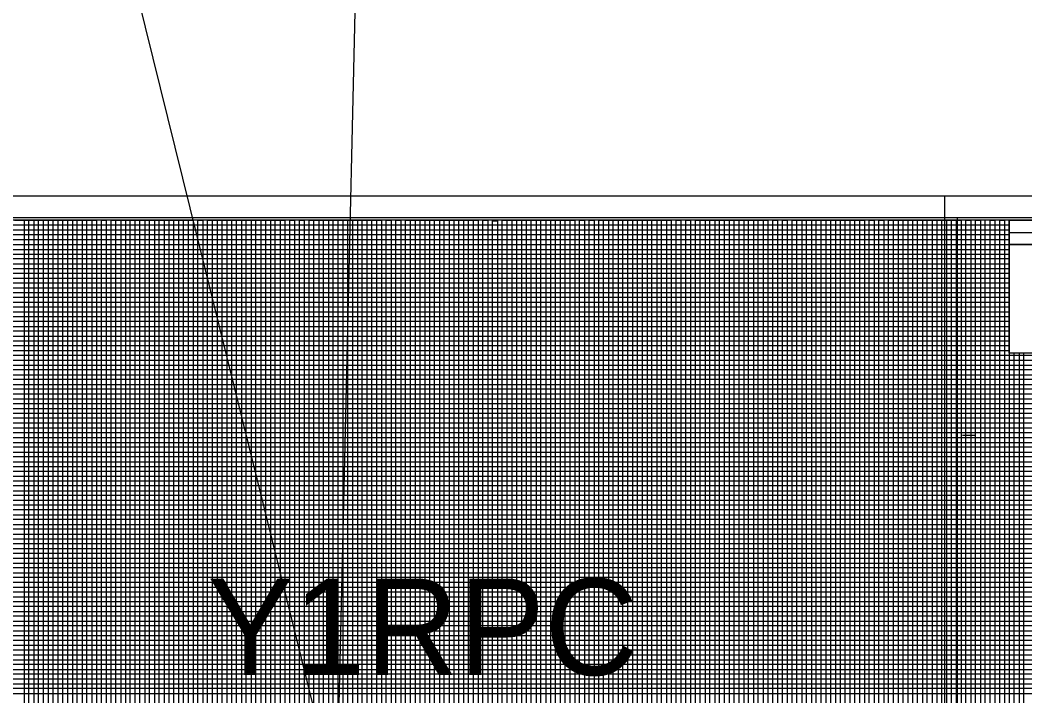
# Model space of a CAD drawing. Extents: x 2345490 to 2436403, y 465165 to 573888.
# Drawn here: x 2411121 to 2412161, y 509253 to 509953 of the extents above; entities that cross this region are included whole.
import ezdxf

# ---------------------------------------------------------------- set-up
doc = ezdxf.new("R2010")
doc.units = 0
for name, color, linetype in [('Old_Level_18', 7, 'Continuous'), ('Old_Level_2', 7, 'Continuous'), ('Old_Level_3', 7, 'Continuous'), ('Old_Level_40', 7, 'Continuous'), ('Old_Level_41', 7, 'Continuous'), ('Old_Level_42', 7, 'Continuous'), ('Old_Level_43', 7, 'Continuous'), ('Old_Level_50', 7, 'Continuous'), ('Old_Level_51', 7, 'Continuous')]:
    doc.layers.add(name, color=color, linetype=linetype)

msp = doc.modelspace()

# ---------------------------------------------------------------- linework, layer by layer
at = {"layer": 'Old_Level_18'}
msp.add_lwpolyline([(2412345.325, 509745.412), (2410845.325, 509745.412), (2410845.325, 508695.412), (2412345.325, 508695.412)], close=True, dxfattribs=at)
at = {"layer": 'Old_Level_2'}
for p, q in [((2408459.41, 521238.414), (2413898.04625, 499235.39575)), ((2411722.59175, 521117.51825), (2411239.1575, 499960.77))]:
    msp.add_line(p, q, dxfattribs=at)
at = {"layer": 'Old_Level_40'}
msp.add_line((2412145.275, 509732.862), (2412345.325, 509732.862), dxfattribs=at)
for points in [[(2412145.275, 509745.412), (2412345.325, 509745.412), (2412345.325, 509720.362), (2412145.275, 509720.362)], [(2412145.275, 509720.362), (2412245.325, 509720.362), (2412245.325, 509607.862), (2412145.275, 509607.862)]]:
    msp.add_lwpolyline(points, close=True, dxfattribs=at)
at = {"layer": 'Old_Level_41'}
msp.add_line((2412096.825, 509522.912), (2412109.325, 509522.912), dxfattribs=at)
for points in [[(2411120.325, 509745.412), (2411170.325, 509745.412), (2411170.325, 508720.412)], [(2411145.325, 508720.412), (2411145.325, 509745.412), (2411195.325, 509745.412), (2411195.325, 508720.412)], [(2411220.325, 508720.412), (2411220.325, 509745.412), (2411270.325, 509745.412), (2411270.325, 508720.412)], [(2411245.325, 508720.412), (2411245.325, 509745.412), (2411295.325, 509745.412), (2411295.325, 508720.412)], [(2411320.325, 508720.412), (2411320.325, 509745.412), (2411370.325, 509745.412), (2411370.325, 508720.412)], [(2411345.325, 508720.412), (2411345.325, 509745.412), (2411395.325, 509745.412), (2411395.325, 508720.412)], [(2411420.325, 508720.412), (2411420.325, 509745.412), (2411470.325, 509745.412), (2411470.325, 508720.412)], [(2411445.325, 508720.412), (2411445.325, 509745.412), (2411495.325, 509745.412), (2411495.325, 508720.412)], [(2411520.325, 508720.412), (2411520.325, 509745.412), (2411570.325, 509745.412), (2411570.325, 508720.412)], [(2411545.325, 508720.412), (2411545.325, 509745.412), (2411595.325, 509745.412), (2411595.325, 508720.412)], [(2411620.325, 508720.412), (2411620.325, 509745.412), (2411670.325, 509745.412), (2411670.325, 508720.412)], [(2411645.325, 508720.412), (2411645.325, 509745.412), (2411695.325, 509745.412), (2411695.325, 508720.412)], [(2411720.325, 508720.412), (2411720.325, 509745.412), (2411770.325, 509745.412), (2411770.325, 508720.412)], [(2411745.325, 508720.412), (2411745.325, 509745.412), (2411795.325, 509745.412), (2411795.325, 508720.412)], [(2411820.325, 508720.412), (2411820.325, 509745.412), (2411870.325, 509745.412), (2411870.325, 508720.412)], [(2411845.325, 508720.412), (2411845.325, 509745.412), (2411895.325, 509745.412), (2411895.325, 508720.412)], [(2411920.325, 508720.412), (2411920.325, 509745.412), (2411970.325, 509745.412), (2411970.325, 508720.412)], [(2411945.325, 508720.412), (2411945.325, 509745.412), (2411995.325, 509745.412), (2411995.325, 508720.412)], [(2412020.325, 508720.412), (2412020.325, 509745.412), (2412070.325, 509745.412), (2412070.325, 508720.412)], [(2412045.325, 508720.412), (2412045.325, 509745.412), (2412095.325, 509745.412), (2412095.325, 508720.412)], [(2412120.325, 508720.412), (2412120.325, 509745.412)], [(2412145.325, 508720.412), (2412145.325, 509745.412), (2412171.625, 509745.412)], [(2410845.325, 509695.412), (2412145.275, 509695.412)], [(2412145.275, 509645.412), (2410845.325, 509645.412), (2410845.325, 509595.362), (2412345.325, 509595.362)], [(2412345.325, 509570.412), (2410845.325, 509570.412), (2410845.325, 509620.412), (2412145.275, 509620.412)], [(2412345.325, 509545.412), (2410845.325, 509545.412), (2410845.325, 509495.412), (2412345.325, 509495.412)], [(2412345.325, 509470.412), (2410845.325, 509470.412), (2410845.325, 509520.412), (2412345.325, 509520.412)], [(2412345.325, 509445.412), (2410845.325, 509445.412), (2410845.325, 509395.412), (2412345.325, 509395.412)], [(2412345.325, 509345.412), (2410845.325, 509345.412), (2410845.325, 509295.412), (2412345.325, 509295.412)]]:
    msp.add_lwpolyline(points, dxfattribs=at)
at = {"layer": 'Old_Level_42'}
for points in [[(2412145.275, 509670.412), (2410845.425, 509670.412), (2410845.425, 509720.362), (2412145.275, 509720.362)], [(2412345.325, 509370.412), (2410845.325, 509370.412), (2410845.325, 509420.412), (2412345.325, 509420.412)], [(2412345.325, 509270.412), (2410845.325, 509270.412), (2410845.325, 509320.412), (2412345.325, 509320.412)]]:
    msp.add_lwpolyline(points, dxfattribs=at)
at = {"layer": 'Old_Level_43'}
for p, q in [((2412295.325, 509565.412), (2410895.325, 509565.412)), ((2410895.325, 509560.412), (2412295.325, 509560.412)), ((2412295.325, 509540.412), (2410895.325, 509540.412))]:
    msp.add_line(p, q, dxfattribs=at)
for points in [[(2411115.325, 509745.412), (2411125.325, 509745.412), (2411125.325, 508720.412)], [(2411130.325, 508720.412), (2411130.325, 509745.412), (2411135.325, 509745.412), (2411135.325, 508720.412)], [(2411140.325, 508720.412), (2411140.325, 509745.412), (2411150.325, 509745.412), (2411150.325, 508720.412)], [(2411155.325, 508720.412), (2411155.325, 509745.412), (2411160.325, 509745.412), (2411160.325, 508720.412)], [(2411165.325, 508720.412), (2411165.325, 509745.412), (2411175.325, 509745.412), (2411175.325, 508720.412)], [(2411180.325, 508720.412), (2411180.325, 509745.412), (2411185.325, 509745.412), (2411185.325, 508720.412)], [(2411190.325, 508720.412), (2411190.325, 509745.412), (2411200.325, 509745.412), (2411200.325, 508720.412)], [(2411205.325, 508720.412), (2411205.325, 509745.412), (2411210.325, 509745.412), (2411210.325, 508720.412)], [(2411215.325, 508720.412), (2411215.325, 509745.412), (2411225.325, 509745.412), (2411225.325, 508720.412)], [(2411230.325, 509745.412), (2411230.325, 508720.412), (2411235.325, 508720.412), (2411235.325, 509745.412)], [(2411240.325, 508720.412), (2411240.325, 509745.412), (2411250.325, 509745.412), (2411250.325, 508720.412)], [(2411255.325, 508720.412), (2411255.325, 509745.412), (2411260.325, 509745.412), (2411260.325, 508720.412)], [(2411265.325, 508720.412), (2411265.325, 509745.412), (2411275.325, 509745.412), (2411275.325, 508720.412)], [(2411280.325, 508720.412), (2411280.325, 509745.412), (2411285.325, 509745.412), (2411285.325, 508720.412)], [(2411290.325, 508720.412), (2411290.325, 509745.412), (2411300.325, 509745.412), (2411300.325, 508720.412)], [(2411305.325, 508720.412), (2411305.325, 509745.412), (2411310.325, 509745.412), (2411310.325, 508720.412)], [(2411315.325, 508720.412), (2411315.325, 509745.412), (2411325.325, 509745.412), (2411325.325, 508720.412)], [(2411330.325, 508720.412), (2411330.325, 509745.412), (2411335.325, 509745.412), (2411335.325, 508720.412)], [(2411340.325, 508720.412), (2411340.325, 509745.412), (2411350.325, 509745.412), (2411350.325, 508720.412)], [(2411355.325, 508720.412), (2411355.325, 509745.412), (2411360.325, 509745.412), (2411360.325, 508720.412)], [(2411365.325, 508720.412), (2411365.325, 509745.412), (2411375.325, 509745.412), (2411375.325, 508720.412)], [(2411380.325, 509745.412), (2411380.325, 508720.412), (2411385.325, 508720.412), (2411385.325, 509745.412), (2411390.325, 509745.412), (2411390.325, 508720.412), (2411400.325, 508720.412), (2411400.325, 509745.412), (2411405.325, 509745.412), (2411405.325, 508720.412), (2411410.325, 508720.412), (2411410.325, 509745.412), (2411415.325, 509745.412), (2411415.325, 508720.412)], [(2411425.325, 508720.412), (2411425.325, 509745.412), (2411430.325, 509745.412), (2411430.325, 508720.412)], [(2411435.325, 508720.412), (2411435.325, 509745.412), (2411440.325, 509745.412), (2411440.325, 508720.412)], [(2411450.325, 508720.412), (2411450.325, 509745.412), (2411455.325, 509745.412), (2411455.325, 508720.412)], [(2411460.325, 508720.412), (2411460.325, 509745.412), (2411465.325, 509745.412), (2411465.325, 508720.412)], [(2411475.325, 508720.412), (2411475.325, 509745.412), (2411480.325, 509745.412), (2411480.325, 508720.412)], [(2411485.325, 508720.412), (2411485.325, 509745.412), (2411490.325, 509745.412), (2411490.325, 508720.412)], [(2411500.325, 508720.412), (2411500.325, 509745.412), (2411505.325, 509745.412), (2411505.325, 508720.412)], [(2411510.325, 508720.412), (2411510.325, 509745.412), (2411515.325, 509745.412), (2411515.325, 508720.412)], [(2411525.325, 508720.412), (2411525.325, 509745.412), (2411530.325, 509745.412), (2411530.325, 508720.412)], [(2411535.325, 508720.412), (2411535.325, 509745.412), (2411540.325, 509745.412), (2411540.325, 508720.412)], [(2411550.325, 508720.412), (2411550.325, 509745.412), (2411555.325, 509745.412), (2411555.325, 508720.412)], [(2411560.325, 508720.412), (2411560.325, 509745.412), (2411565.325, 509745.412), (2411565.325, 508720.412)], [(2411575.325, 508720.412), (2411575.325, 509745.412), (2411580.325, 509745.412), (2411580.325, 508720.412)], [(2411585.325, 508720.412), (2411585.325, 509745.412), (2411590.325, 509745.412), (2411590.325, 508720.412)], [(2411600.325, 508720.412), (2411600.325, 509745.412), (2411605.325, 509745.412), (2411605.325, 508720.412)], [(2411625.325, 508720.412), (2411625.325, 509745.412), (2411630.325, 509745.412), (2411630.325, 508720.412)], [(2411635.325, 508720.412), (2411635.325, 509745.412), (2411640.325, 509745.412), (2411640.325, 508720.412)], [(2411650.325, 508720.412), (2411650.325, 509745.412), (2411655.325, 509745.412), (2411655.325, 508720.412)], [(2411660.325, 508720.412), (2411660.325, 509745.412), (2411665.325, 509745.412), (2411665.325, 508720.412)], [(2411675.325, 508720.412), (2411675.325, 509745.412), (2411680.325, 509745.412), (2411680.325, 508720.412)], [(2411685.325, 508720.412), (2411685.325, 509745.412), (2411690.325, 509745.412), (2411690.325, 508720.412)], [(2411700.325, 508720.412), (2411700.325, 509745.412), (2411705.325, 509745.412), (2411705.325, 508720.412)], [(2411710.325, 508720.412), (2411710.325, 509745.412), (2411715.325, 509745.412), (2411715.325, 508720.412)], [(2411725.325, 508720.412), (2411725.325, 509745.412), (2411730.325, 509745.412), (2411730.325, 508720.412)], [(2411735.325, 508720.412), (2411735.325, 509745.412), (2411740.325, 509745.412), (2411740.325, 508720.412)], [(2411750.325, 508720.412), (2411750.325, 509745.412), (2411755.325, 509745.412), (2411755.325, 508720.412)], [(2411760.325, 508720.412), (2411760.325, 509745.412), (2411765.325, 509745.412), (2411765.325, 508720.412)], [(2411775.325, 508720.412), (2411775.325, 509745.412), (2411780.325, 509745.412), (2411780.325, 508720.412)], [(2411785.325, 508720.412), (2411785.325, 509745.412), (2411790.325, 509745.412), (2411790.325, 508720.412)], [(2411800.325, 508720.412), (2411800.325, 509745.412), (2411805.325, 509745.412), (2411805.325, 508720.412)], [(2411810.325, 508720.412), (2411810.325, 509745.412), (2411815.325, 509745.412), (2411815.325, 508720.412)], [(2411825.325, 508720.412), (2411825.325, 509745.412), (2411830.325, 509745.412), (2411830.325, 508720.412)], [(2411835.325, 508720.412), (2411835.325, 509745.412), (2411840.325, 509745.412), (2411840.325, 508720.412)], [(2411850.325, 508720.412), (2411850.325, 509745.412), (2411855.325, 509745.412), (2411855.325, 508720.412)], [(2411860.325, 508720.412), (2411860.325, 509745.412), (2411865.325, 509745.412), (2411865.325, 508720.412)], [(2411875.325, 508720.412), (2411875.325, 509745.412), (2411880.325, 509745.412), (2411880.325, 508720.412)], [(2411885.325, 508720.412), (2411885.325, 509745.412), (2411890.325, 509745.412), (2411890.325, 508720.412)], [(2411900.325, 508720.412), (2411900.325, 509745.412), (2411905.325, 509745.412), (2411905.325, 508720.412)], [(2411910.325, 508720.412), (2411910.325, 509745.412), (2411915.325, 509745.412), (2411915.325, 508720.412)], [(2411925.325, 508720.412), (2411925.325, 509745.412), (2411930.325, 509745.412), (2411930.325, 508720.412)], [(2411935.325, 508720.412), (2411935.325, 509745.412), (2411940.325, 509745.412), (2411940.325, 508720.412)], [(2411950.325, 508720.412), (2411950.325, 509745.412), (2411955.325, 509745.412), (2411955.325, 508720.412)], [(2411960.325, 508720.412), (2411960.325, 509745.412), (2411965.325, 509745.412), (2411965.325, 508720.412)], [(2411975.325, 508720.412), (2411975.325, 509745.412), (2411980.325, 509745.412), (2411980.325, 508720.412)], [(2411985.325, 508720.412), (2411985.325, 509745.412), (2411990.325, 509745.412), (2411990.325, 508720.412)], [(2412000.325, 508720.412), (2412000.325, 509745.412), (2412005.325, 509745.412), (2412005.325, 508720.412)], [(2412010.325, 508720.412), (2412010.325, 509745.412), (2412015.325, 509745.412), (2412015.325, 508720.412)], [(2412025.325, 508720.412), (2412025.325, 509745.412), (2412030.325, 509745.412), (2412030.325, 508720.412)], [(2412035.325, 508720.412), (2412035.325, 509745.412), (2412040.325, 509745.412), (2412040.325, 508720.412)], [(2412050.325, 508720.412), (2412050.325, 509745.412), (2412055.325, 509745.412), (2412055.325, 508720.412)], [(2412060.325, 508720.412), (2412060.325, 509745.412), (2412065.325, 509745.412), (2412065.325, 508720.412)], [(2412075.325, 508720.412), (2412075.325, 509745.412), (2412080.325, 509745.412), (2412080.325, 508720.412)], [(2412085.325, 508720.412), (2412085.325, 509745.412), (2412090.325, 509745.412), (2412090.325, 508720.412)], [(2412100.325, 508720.412), (2412100.325, 509745.412), (2412105.325, 509745.412), (2412105.325, 508720.412)], [(2412110.325, 508720.412), (2412110.325, 509745.412), (2412115.325, 509745.412), (2412115.325, 508720.412)], [(2412125.325, 508720.412), (2412125.325, 509745.412), (2412130.325, 509745.412), (2412130.325, 508720.412)], [(2412135.325, 508720.412), (2412135.325, 509745.412), (2412140.325, 509745.412), (2412140.325, 508720.412)], [(2412145.275, 509740.412), (2410895.325, 509740.412), (2410895.325, 509735.412), (2412145.275, 509735.412)], [(2411230.325, 509744.812), (2411230.325, 508720.412), (2411235.325, 508720.412), (2411235.325, 509744.812)], [(2411610.325, 508720.412), (2411610.325, 509744.812), (2411615.325, 509744.812), (2411615.325, 508720.412)], [(2412145.275, 509730.412), (2410895.325, 509730.412), (2410895.325, 509725.412), (2412145.275, 509725.412)], [(2412145.275, 509714.662), (2410896.325, 509714.662), (2410896.325, 509710.412), (2412145.275, 509710.412)], [(2412145.275, 509705.412), (2410895.325, 509705.412), (2410895.325, 509700.412), (2412145.275, 509700.412)], [(2412145.275, 509690.412), (2410895.325, 509690.412), (2410895.325, 509685.412), (2412145.275, 509685.412)], [(2412145.275, 509680.412), (2410895.325, 509680.412), (2410895.325, 509675.412), (2412145.275, 509675.412)], [(2412145.275, 509665.412), (2410895.325, 509665.412), (2410895.325, 509660.412), (2412145.275, 509660.412)], [(2412145.275, 509655.412), (2410895.325, 509655.412), (2410895.325, 509650.412), (2412145.275, 509650.412)], [(2412145.275, 509640.412), (2410895.325, 509640.412), (2410895.325, 509635.412), (2412145.275, 509635.412)], [(2412145.275, 509630.412), (2410895.325, 509630.412), (2410895.325, 509625.412), (2412145.275, 509625.412)], [(2412145.275, 509615.412), (2410895.325, 509615.412), (2410895.325, 509610.412), (2412145.275, 509610.412)], [(2412295.325, 509605.412), (2410895.325, 509605.412), (2410895.325, 509605.412), (2410895.325, 509585.412), (2412295.325, 509585.412)], [(2410895.325, 509600.412), (2412295.325, 509600.412)], [(2412150.325, 508720.412), (2412150.325, 509607.862)], [(2412155.325, 509607.862), (2412155.325, 508720.412), (2412160.325, 508720.412), (2412160.325, 509607.862)], [(2412295.325, 509590.412), (2410895.325, 509590.412)], [(2412295.325, 509580.412), (2410895.325, 509580.412), (2410895.325, 509575.412), (2412295.325, 509575.412)], [(2412295.325, 509555.412), (2410895.325, 509555.412), (2410895.325, 509550.412), (2412295.325, 509550.412)], [(2412295.325, 509535.412), (2410895.325, 509535.412), (2410895.325, 509530.412), (2412295.325, 509530.412)], [(2412295.325, 509525.412), (2410895.325, 509525.412)], [(2410895.325, 509515.412), (2412295.325, 509515.412)], [(2412295.325, 509510.412), (2410895.325, 509510.412), (2410895.325, 509505.412), (2412295.325, 509505.412)], [(2412295.325, 509500.412), (2410895.325, 509500.412), (2410895.325, 509490.412), (2412295.325, 509490.412)], [(2412295.325, 509485.412), (2410895.325, 509485.412), (2410895.325, 509480.412), (2412295.325, 509480.412)], [(2412295.325, 509475.412), (2410895.325, 509475.412), (2410895.325, 509465.412), (2412295.325, 509465.412)], [(2412295.325, 509460.412), (2410895.325, 509460.412), (2410895.325, 509455.412), (2412295.325, 509455.412)], [(2412295.325, 509450.412), (2410895.325, 509450.412), (2410895.325, 509440.412), (2412295.325, 509440.412)], [(2412295.325, 509435.412), (2410895.325, 509435.412), (2410895.325, 509430.412), (2412295.325, 509430.412)], [(2412295.325, 509425.412), (2410895.325, 509425.412), (2410895.325, 509415.412), (2412295.325, 509415.412)], [(2412295.325, 509410.412), (2410895.325, 509410.412), (2410895.325, 509405.412), (2412295.325, 509405.412)], [(2412295.325, 509400.412), (2410895.325, 509400.412), (2410895.325, 509390.412), (2412295.325, 509390.412)], [(2412295.325, 509385.412), (2410895.325, 509385.412), (2410895.325, 509380.412), (2412295.325, 509380.412)], [(2412295.325, 509375.412), (2410895.325, 509375.412), (2410895.325, 509365.412), (2412295.325, 509365.412)], [(2412295.325, 509360.412), (2410895.325, 509360.412), (2410895.325, 509355.412), (2412295.325, 509355.412)], [(2412295.325, 509350.412), (2410895.325, 509350.412), (2410895.325, 509340.412), (2412295.325, 509340.412)], [(2412295.325, 509335.412), (2410895.325, 509335.412), (2410895.325, 509330.412), (2412295.325, 509330.412)], [(2412295.325, 509325.412), (2410895.325, 509325.412), (2410895.325, 509315.412), (2412295.325, 509315.412)], [(2412295.325, 509310.412), (2410895.325, 509310.412), (2410895.325, 509305.412), (2412295.325, 509305.412)], [(2412295.325, 509300.412), (2410895.325, 509300.412), (2410895.325, 509290.412), (2412295.325, 509290.412)], [(2412295.325, 509285.412), (2410895.325, 509285.412), (2410895.325, 509280.412), (2412295.325, 509280.412)], [(2412295.325, 509275.412), (2410895.325, 509275.412), (2410895.325, 509265.412), (2412295.325, 509265.412)], [(2412295.325, 509260.412), (2410895.325, 509260.412), (2410895.325, 509255.412), (2412295.325, 509255.412)]]:
    msp.add_lwpolyline(points, dxfattribs=at)
at = {"layer": 'Old_Level_50'}
for points in [[(2412357.825, 509747.962), (2410691.325, 509747.962), (2410691.325, 508692.862), (2412357.825, 508692.862)], [(2413757.825, 509747.962), (2412091.325, 509747.962), (2412091.325, 508692.862), (2413757.825, 508692.862)]]:
    msp.add_lwpolyline(points, close=True, dxfattribs=at)
at = {"layer": 'Old_Level_51'}
for points in [[(2412362.325, 509770.412), (2410678.325, 509770.412), (2410678.325, 508670.412), (2412362.325, 508670.412)], [(2413762.325, 509770.412), (2412078.325, 509770.412), (2412078.325, 508670.412), (2413762.325, 508670.412)]]:
    msp.add_lwpolyline(points, close=True, dxfattribs=at)

# ---------------------------------------------------------------- texts
at = {"layer": 'Old_Level_3'}
msp.add_text('Y1RPC', height=99.999999, dxfattribs=at).set_placement((2411315.0005, 509274.4045))

doc.saveas('drawing.dxf')
